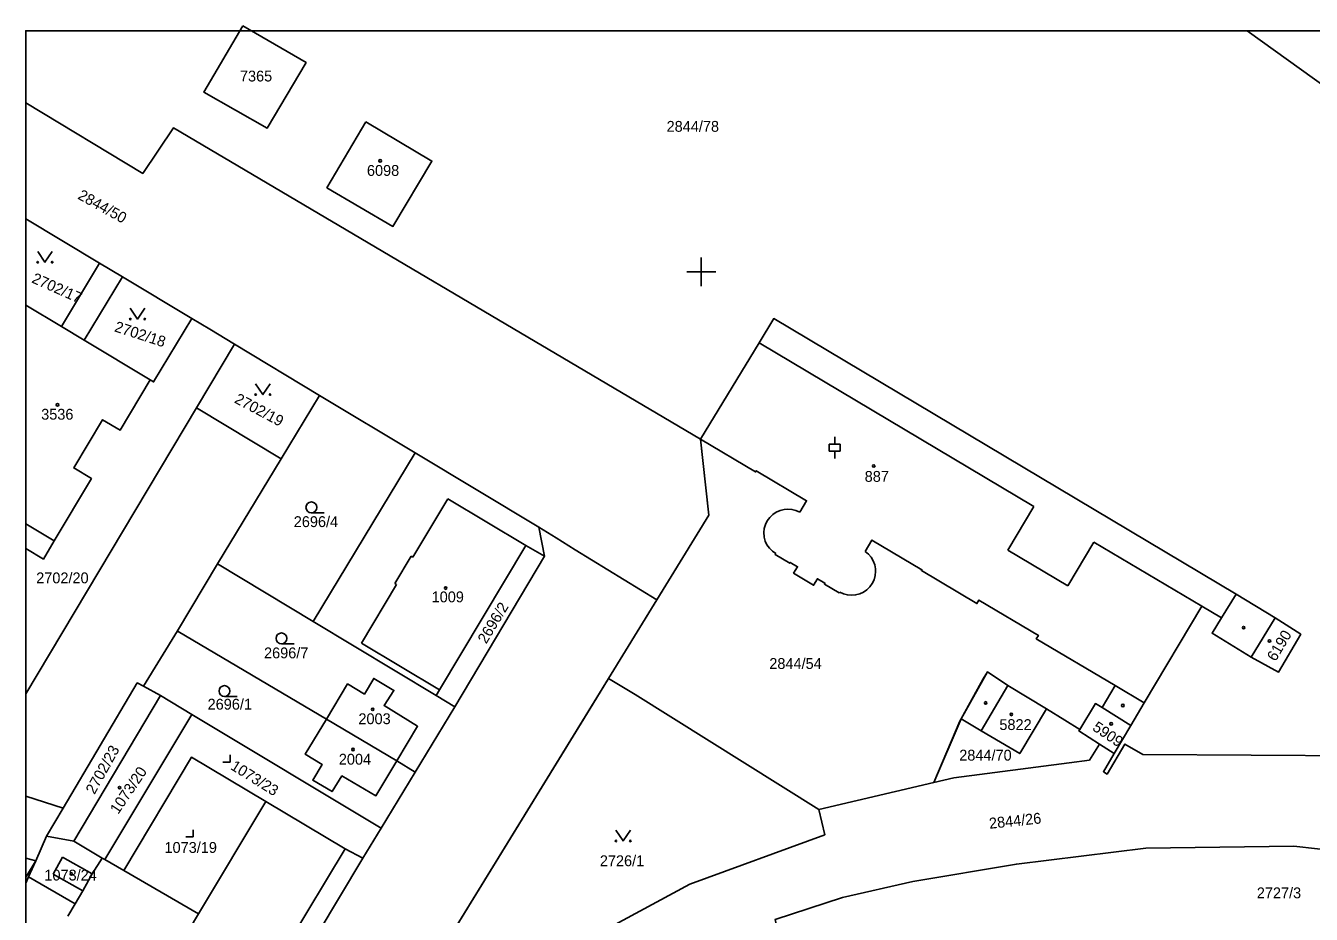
# Model space of a CAD drawing. Extents: x -800194 to -799297, y -1007177 to -1006761.
# Drawn here: x -800193.4 to -800015.7, y -1006888.9 to -1006766 of the extents above; entities that cross this region are included whole.
import ezdxf

# ---------------------------------------------------------------- set-up
doc = ezdxf.new("R2010")
doc.units = 0
for name, color, linetype in [('Legenda 1', 7, 'Continuous'), ('Ramove udaje', 7, 'Continuous'), ('Vrstva 53', 7, 'Continuous'), ('Vrstva 55', 7, 'Continuous'), ('Vrstva 56', 7, 'Continuous'), ('Vrstva 57', 7, 'Continuous'), ('Vrstva 58', 7, 'Continuous'), ('Vrstva 59', 7, 'Continuous')]:
    doc.layers.add(name, color=color, linetype=linetype)

msp = doc.modelspace()

# ---------------------------------------------------------------- linework, layer by layer
at = {"layer": 'Legenda 1'}
msp.add_lwpolyline([(-800193.4, -1007176.65), (-799312.4, -1007176.65), (-799312.4, -1006766.65), (-800193.4, -1006766.65)], close=True, dxfattribs=at)
at = {"layer": 'Ramove udaje'}
for p, q in [((-800100, -1006798), (-800100, -1006802)), ((-800102, -1006800), (-800100, -1006800)), ((-800100, -1006800), (-800098, -1006800))]:
    msp.add_line(p, q, dxfattribs=at)
at = {"layer": 'Vrstva 53'}
for points in [[(-800147.15, -1006912.2), (-800112.81, -1006856.29), (-800098.93, -1006833.67), (-800100.11, -1006823.15), (-800172.96, -1006780.08), (-800177.22, -1006786.39), (-800193.4, -1006776.62)], [(-800009, -1006866.96), (-800038.94, -1006866.77), (-800041.43, -1006865.34), (-800043.88, -1006869.49), (-800044.4, -1006869.18), (-800042.89, -1006866.63), (-800044.93, -1006865.34), (-800047.78, -1006863.53), (-800047.67, -1006863.34), (-800049.72, -1006862.02), (-800052.27, -1006860.45), (-800057.6, -1006857.24), (-800060.43, -1006855.37), (-800064.08, -1006861.85), (-800067.83, -1006870.66), (-800083.75, -1006874.38), (-800082.93, -1006877.89), (-800101.58, -1006884.73), (-800119.41, -1006894.35)]]:
    msp.add_lwpolyline(points, dxfattribs=at)
at = {"layer": 'Vrstva 55'}
for p, q in [((-800024.53, -1006766.65), (-799970.63, -1006805.46)), ((-800183.18, -1006798.79), (-800193.4, -1006792.65)), ((-800180.01, -1006800.69), (-800183.18, -1006798.79)), ((-800170.41, -1006806.46), (-800180.01, -1006800.69)), ((-800164.51, -1006810.02), (-800169.77, -1006818.83)), ((-800152.8, -1006817.1), (-800164.51, -1006810.02)), ((-800152.8, -1006817.1), (-800158.09, -1006825.87)), ((-800139.57, -1006825.06), (-800152.8, -1006817.1)), ((-800158.09, -1006825.87), (-800169.77, -1006818.83)), ((-800139.57, -1006825.06), (-800153.65, -1006848.37)), ((-800122.47, -1006835.35), (-800139.57, -1006825.06)), ((-800158.09, -1006825.87), (-800166.86, -1006840.41)), ((-800122.47, -1006835.35), (-800121.67, -1006839.36)), ((-800121.67, -1006839.36), (-800134.05, -1006860.17)), ((-800166.86, -1006840.41), (-800172.41, -1006849.68)), ((-800166.86, -1006840.41), (-800153.65, -1006848.37)), ((-800112.81, -1006856.29), (-800106.13, -1006845.4)), ((-800023.97, -1006853.3), (-800020.66, -1006847.86)), ((-800172.41, -1006849.68), (-800177.12, -1006857.35)), ((-800153.65, -1006848.37), (-800136.64, -1006858.61)), ((-800174.74, -1006858.64), (-800186.75, -1006878.76)), ((-800177.12, -1006857.35), (-800174.74, -1006858.64)), ((-800170.43, -1006861.26), (-800174.74, -1006858.64)), ((-800136.64, -1006858.61), (-800134.05, -1006860.17)), ((-800042.78, -1006857.25), (-800038.76, -1006859.64)), ((-800134.05, -1006860.17), (-800139.55, -1006869.21)), ((-800182.47, -1006881.33), (-800170.43, -1006861.26)), ((-800144.27, -1006876.97), (-800170.43, -1006861.26)), ((-800151.83, -1006861.89), (-800142.1, -1006867.68)), ((-800042.89, -1006866.63), (-800044.93, -1006865.34)), ((-800139.55, -1006869.21), (-800142.1, -1006867.68)), ((-800139.55, -1006869.21), (-800144.27, -1006876.97)), ((-800067.83, -1006870.66), (-800083.75, -1006874.38)), ((-800193.4, -1006872.57), (-800188.22, -1006874.2)), ((-800188.22, -1006874.2), (-800190.53, -1006878.1)), ((-800160.18, -1006873.27), (-800169.49, -1006888.81)), ((-800190.53, -1006878.1), (-800192.02, -1006881.48)), ((-800186.75, -1006878.76), (-800190.53, -1006878.1)), ((-800144.27, -1006876.97), (-800146.81, -1006881.14)), ((-800186.75, -1006878.76), (-800182.83, -1006881.12)), ((-800192.02, -1006881.48), (-800193.4, -1006881.15)), ((-800192.02, -1006881.48), (-800193.01, -1006883.73)), ((-800182.83, -1006881.12), (-800182.47, -1006881.33)), ((-800179.85, -1006882.84), (-800182.47, -1006881.33)), ((-800193.4, -1006884.61), (-800193.01, -1006883.73)), ((-800193.01, -1006883.73), (-800186.55, -1006887.44)), ((-800179.85, -1006882.84), (-800169.49, -1006888.81)), ((-800186.55, -1006887.44), (-800187.59, -1006889.15)), ((-800169.49, -1006888.81), (-800182.05, -1006909.75))]:
    msp.add_line(p, q, dxfattribs=at)
for points in [[(-800163.38, -1006765.95), (-800154.63, -1006771.06), (-800160.01, -1006780.11), (-800168.77, -1006775.17), (-800163.38, -1006765.95)], [(-800100.11, -1006823.15), (-800172.96, -1006780.08), (-800177.22, -1006786.39), (-800193.4, -1006776.62)], [(-800146.37, -1006779.25), (-800137.24, -1006784.69), (-800142.62, -1006793.72), (-800151.76, -1006788.38), (-800146.37, -1006779.25)], [(-800183.18, -1006798.79), (-800188.44, -1006807.58), (-800193.4, -1006804.6)], [(-800176.19, -1006814.96), (-800185.31, -1006809.46), (-800180.01, -1006800.69)], [(-800176.19, -1006814.96), (-800175.72, -1006815.24), (-800170.41, -1006806.46)], [(-800164.51, -1006810.02), (-800167.92, -1006807.96), (-800170.41, -1006806.46)], [(-800020.66, -1006847.86), (-800026.06, -1006844.58), (-800089.97, -1006806.47), (-800092.01, -1006809.83), (-800100.11, -1006823.15)], [(-800193.4, -1006838.29), (-800190.96, -1006839.75), (-800189.46, -1006837.23), (-800184.32, -1006828.6), (-800186.75, -1006827.14), (-800182.78, -1006820.48), (-800180.34, -1006821.93), (-800176.19, -1006814.96)], [(-800169.77, -1006818.83), (-800193.4, -1006858.41)], [(-800106.13, -1006845.4), (-800098.93, -1006833.67), (-800099.83, -1006825.69), (-800100.11, -1006823.15)], [(-800100.11, -1006823.15), (-800092.48, -1006827.68), (-800092.4, -1006827.53), (-800085.43, -1006831.67), (-800086.36, -1006833.24)], [(-800086.36, -1006833.24), (-800086.9, -1006833.01), (-800087.46, -1006832.87), (-800088.05, -1006832.83), (-800088.53, -1006832.88), (-800089.09, -1006833.02), (-800089.63, -1006833.26), (-800090.11, -1006833.59), (-800090.53, -1006833.99), (-800090.88, -1006834.46), (-800091.13, -1006834.97), (-800091.29, -1006835.52), (-800091.35, -1006836.09), (-800091.31, -1006836.66), (-800091.3, -1006836.72), (-800091.15, -1006837.27), (-800090.91, -1006837.79), (-800090.58, -1006838.25), (-800090.17, -1006838.66), (-800089.7, -1006838.98)], [(-800106.13, -1006845.4), (-800117.43, -1006838.45), (-800120.08, -1006836.82), (-800122.47, -1006835.35)], [(-800077.33, -1006838.69), (-800076.4, -1006837.12), (-800069.48, -1006841.22), (-800069.56, -1006841.35), (-800061.89, -1006845.9), (-800061.61, -1006845.43), (-800053.39, -1006850.31), (-800053.68, -1006850.78), (-800042.78, -1006857.25)], [(-800136.64, -1006858.61), (-800136.18, -1006857.85), (-800124.24, -1006837.87), (-800121.67, -1006839.36)], [(-800089.7, -1006838.98), (-800089.78, -1006839.11), (-800087.76, -1006840.33), (-800087.69, -1006840.2), (-800086.68, -1006840.8), (-800087.24, -1006841.68), (-800084.46, -1006843.37), (-800083.93, -1006842.46), (-800082.91, -1006843.08), (-800082.98, -1006843.21), (-800080.94, -1006844.44), (-800080.86, -1006844.31)], [(-800080.86, -1006844.31), (-800080.34, -1006844.55), (-800079.78, -1006844.7), (-800079.21, -1006844.75), (-800078.65, -1006844.71), (-800078.09, -1006844.56), (-800077.57, -1006844.32), (-800077.09, -1006843.99), (-800076.68, -1006843.59), (-800076.35, -1006843.12), (-800076.1, -1006842.6), (-800075.95, -1006842.04), (-800075.89, -1006841.47), (-800075.91, -1006841.1), (-800076.01, -1006840.53), (-800076.22, -1006839.99), (-800076.51, -1006839.49), (-800076.89, -1006839.06), (-800077.33, -1006838.69)], [(-800038.76, -1006859.64), (-800030.81, -1006846.28), (-800028.08, -1006847.9), (-800029.37, -1006850.02), (-800023.97, -1006853.3)], [(-800020.66, -1006847.86), (-800017.12, -1006850.15), (-800020.18, -1006855.39), (-800023.97, -1006853.3)], [(-800151.83, -1006861.89), (-800172.32, -1006849.75), (-800172.41, -1006849.68)], [(-800064.08, -1006861.85), (-800061.02, -1006856.31), (-800060.43, -1006855.37), (-800057.6, -1006857.24), (-800052.27, -1006860.45)], [(-800188.22, -1006874.2), (-800177.98, -1006856.88), (-800177.12, -1006857.35)], [(-800142.1, -1006867.68), (-800139.22, -1006862.87), (-800143.86, -1006860.02), (-800142.5, -1006857.92), (-800145.28, -1006856.27), (-800146.57, -1006858.42), (-800148.9, -1006857.02), (-800151.83, -1006861.89)], [(-800147.15, -1006912.2), (-800114.97, -1006859.8), (-800112.81, -1006856.29)], [(-800083.75, -1006874.38), (-800109.15, -1006858.49), (-800112.81, -1006856.29)], [(-800047.67, -1006863.34), (-800045.49, -1006859.74), (-800044.59, -1006860.3), (-800042.78, -1006857.25)], [(-800052.27, -1006860.45), (-800055.96, -1006866.67), (-800061.32, -1006863.49), (-800064.08, -1006861.85)], [(-800052.27, -1006860.45), (-800049.72, -1006862.02), (-800047.67, -1006863.34)], [(-800042.89, -1006866.63), (-800040.61, -1006862.78), (-800038.76, -1006859.64)], [(-800151.83, -1006861.89), (-800154.75, -1006866.76), (-800152.43, -1006868.16), (-800153.72, -1006870.34), (-800151.03, -1006871.91), (-800149.68, -1006869.74), (-800144.98, -1006872.49), (-800142.1, -1006867.68)], [(-800067.83, -1006870.66), (-800064.25, -1006862.16), (-800064.08, -1006861.85)], [(-800047.67, -1006863.34), (-800047.78, -1006863.53), (-800044.93, -1006865.34)], [(-800044.93, -1006865.34), (-800046.33, -1006867.59), (-800049.13, -1006867.95), (-800065.09, -1006870.02), (-800067.83, -1006870.66)], [(-799964.79, -1006890.84), (-799981.37, -1006872.46), (-800005.05, -1006867.41), (-800009, -1006866.96), (-800038.94, -1006866.77), (-800041.43, -1006865.34), (-800043.88, -1006869.49), (-800044.4, -1006869.18), (-800042.89, -1006866.63)], [(-800160.18, -1006873.27), (-800170.48, -1006867.17), (-800179.85, -1006882.84)], [(-800146.81, -1006881.14), (-800149.24, -1006879.83), (-800160.18, -1006873.27)], [(-800144.92, -1006913.85), (-800133.89, -1006904.78), (-800119.41, -1006894.35), (-800101.58, -1006884.73), (-800082.93, -1006877.89), (-800083.75, -1006874.38)], [(-799964.79, -1006890.84), (-799979.01, -1006885.96), (-799998.45, -1006881.67), (-800018.08, -1006879.48), (-800038.51, -1006879.76), (-800056.43, -1006881.95), (-800070.76, -1006884.38), (-800080.47, -1006886.59), (-800089.79, -1006889.63), (-800088.91, -1006893.34), (-800105.12, -1006899.41), (-800124.67, -1006911.59), (-800137.62, -1006920.11), (-800154.3, -1006934.53), (-800165.04, -1006947.7)], [(-800193.4, -1006883.76), (-800192.02, -1006881.48)], [(-800182.83, -1006881.12), (-800184.21, -1006883.32), (-800185.51, -1006885.63), (-800186.55, -1006887.44)], [(-800146.81, -1006881.14), (-800156.19, -1006896.85), (-800168.72, -1006917.84)]]:
    msp.add_lwpolyline(points, dxfattribs=at)
at = {"layer": 'Vrstva 56'}
for p, q in [((-800188.44, -1006807.58), (-800185.31, -1006809.46)), ((-800092.01, -1006809.83), (-800054.01, -1006832.46)), ((-800139.86, -1006839.49), (-800135.03, -1006831.4)), ((-800135.03, -1006831.4), (-800124.24, -1006837.87)), ((-800054.01, -1006832.46), (-800057.61, -1006838.51)), ((-800189.46, -1006837.23), (-800193.4, -1006834.87)), ((-800049.33, -1006843.44), (-800045.73, -1006837.39)), ((-800045.73, -1006837.39), (-800030.81, -1006846.28)), ((-800142.38, -1006843.12), (-800140.12, -1006839.33)), ((-800140.12, -1006839.33), (-800139.86, -1006839.49)), ((-800057.61, -1006838.51), (-800049.33, -1006843.44)), ((-800146.98, -1006851.4), (-800142.12, -1006843.27)), ((-800142.12, -1006843.27), (-800142.38, -1006843.12)), ((-800026.06, -1006844.58), (-800028.08, -1006847.9)), ((-800136.18, -1006857.85), (-800146.98, -1006851.4)), ((-800061.32, -1006863.49), (-800057.6, -1006857.24)), ((-800044.59, -1006860.3), (-800040.61, -1006862.78)), ((-800149.24, -1006879.83), (-800158.6, -1006895.39)), ((-800188.29, -1006880.97), (-800189.61, -1006883.33)), ((-800184.21, -1006883.32), (-800188.29, -1006880.97)), ((-800189.61, -1006883.33), (-800185.51, -1006885.63))]:
    msp.add_line(p, q, dxfattribs=at)
at = {"layer": 'Vrstva 58'}
for p, q in [((-800081.54, -1006823.83), (-800081.54, -1006822.83)), ((-800082.29, -1006823.83), (-800080.79, -1006823.83)), ((-800082.29, -1006824.83), (-800082.29, -1006823.83)), ((-800082.29, -1006824.83), (-800080.79, -1006824.83)), ((-800081.54, -1006825.83), (-800081.54, -1006824.83)), ((-800080.79, -1006824.83), (-800080.79, -1006823.83)), ((-800153.9, -1006833.35), (-800152.15, -1006833.35)), ((-800158.04, -1006851.47), (-800156.29, -1006851.47)), ((-800165.92, -1006858.76), (-800164.17, -1006858.76)), ((-800166.13, -1006867.84), (-800165.12, -1006867.84)), ((-800165.12, -1006867.84), (-800165.12, -1006866.84)), ((-800171.24, -1006878.2), (-800170.24, -1006878.2)), ((-800170.24, -1006878.2), (-800170.24, -1006877.2))]:
    msp.add_line(p, q, dxfattribs=at)
for points in [[(-800191.74, -1006797.17), (-800190.74, -1006798.67), (-800189.74, -1006797.17)], [(-800178.94, -1006805.05), (-800177.94, -1006806.55), (-800176.94, -1006805.05)], [(-800161.61, -1006815.49), (-800160.61, -1006816.99), (-800159.61, -1006815.49)], [(-800111.8, -1006877.25), (-800110.8, -1006878.75), (-800109.8, -1006877.25)]]:
    msp.add_lwpolyline(points, dxfattribs=at)
for centre, radius in [((-800191.74, -1006798.67), 0.1), ((-800189.74, -1006798.67), 0.1), ((-800178.94, -1006806.55), 0.1), ((-800176.94, -1006806.55), 0.1), ((-800161.61, -1006816.99), 0.1), ((-800159.61, -1006816.99), 0.1), ((-800153.9, -1006832.6), 0.75), ((-800158.04, -1006850.72), 0.75), ((-800165.92, -1006858.01), 0.75), ((-800111.8, -1006878.75), 0.1), ((-800109.8, -1006878.75), 0.1)]:
    msp.add_circle(centre, radius, dxfattribs=at)
at = {"layer": 'Vrstva 59'}
for centre in [(-800144.39, -1006784.64), (-800189.01, -1006818.41), (-800076.15, -1006826.87), (-800135.34, -1006843.76), (-800025.01, -1006849.23), (-800021.44, -1006851.08), (-800145.42, -1006860.54), (-800060.68, -1006859.65), (-800041.71, -1006860), (-800057.13, -1006861.24), (-800043.33, -1006862.55), (-800148.15, -1006866.1), (-800180.42, -1006871.38), (-800187.09, -1006883.31)]:
    msp.add_circle(centre, 0.175, dxfattribs=at)

# ---------------------------------------------------------------- texts
at = {"layer": 'Vrstva 57'}
for s, p in [('7365', (-800163.78, -1006773.67)), ('2844/78', (-800104.79, -1006780.63)), ('6098', (-800146.22, -1006786.73)), ('3536', (-800191.26, -1006820.46)), ('887', (-800077.4, -1006829.06)), ('2696/4', (-800156.34, -1006835.32)), ('2702/20', (-800191.95, -1006843.1)), ('1009', (-800137.28, -1006845.73)), ('2696/7', (-800160.45, -1006853.48)), ('2844/54', (-800090.59, -1006854.95)), ('2696/1', (-800168.25, -1006860.58)), ('2003', (-800147.4, -1006862.59)), ('5822', (-800058.78, -1006863.4)), ('2844/70', (-800064.33, -1006867.63)), ('2004', (-800150.11, -1006868.19)), ('1073/19', (-800174.21, -1006880.4)), ('2726/1', (-800114.02, -1006882.24)), ('1073/24', (-800190.82, -1006884.22)), ('2727/3', (-800023.19, -1006886.68))]:
    msp.add_text(s, height=1.5, dxfattribs=at).set_placement(p)
for s, rotation, p in [('2844/50', 331, (-800186.32, -1006789.84)), ('2702/17', 336, (-800192.68, -1006801.44)), ('2702/18', 342, (-800181.24, -1006808.22)), ('2702/19', 332, (-800164.66, -1006818.05)), ('2696/2', 59, (-800129.73, -1006851.57)), ('6190', 59, (-800020.6, -1006854)), ('5909', 326, (-800046.03, -1006863.34)), ('2702/23', 61, (-800183.89, -1006872.4)), ('1073/23', 328, (-800165.2, -1006868.76)), ('1073/20', 56, (-800180.61, -1006875.14)), ('2844/26', 6, (-800060.13, -1006877.07))]:
    msp.add_text(s, height=1.5, rotation=rotation, dxfattribs=at).set_placement(p)

doc.saveas('drawing.dxf')
